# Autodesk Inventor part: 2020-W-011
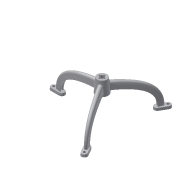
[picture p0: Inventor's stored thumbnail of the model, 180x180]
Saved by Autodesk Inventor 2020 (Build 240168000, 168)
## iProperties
Created: 2013-12
Part Number: 2020-W-011
Material: Tworzywo o ultrawysokiej masie cząsteczkowej, białe
Document SubType Name: Modeling
Designer: F.Stasiak
Density: 0.94 g/cm^3
Appearance: Gładki - biały
Manager: www.cadconsulting.pl
Company: Fabian Stasiak CAD Consulting
Author: F.Stasiak
Subject: Zbiór ćwiczeń. Autodesk Inventor 2020. Kurs podstawowy
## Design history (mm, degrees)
sketch "Szkic1"
  geometry: L1 (20.99, 0)-(-20.99, 0); L2 (-150, -53.809)-(-150, -106.191); A1 r 277.438 centre (0, -277.438) between (16.762, -0.507) and (-16.762, -0.507); A2 r 89.469 centre (-60.531, -80) between (-147.643, -59.599) and (-147.643, -100.401); 3 further points
  constraints: 4 end point, 4 midpoint, 2 centre point, 2 horizontal, 2 point on circle, 2 vertical, 5 other
  dimensions: "d1" = 80 vertical distance of point (-150, -80) point (0, 0); "d2" = 150 horizontal distance of point (-150, -80) point (0, 0)
node "Płaszczyzna konstrukcyjna1"
sketch "Szkic2"
  geometry: L1 (0, -10)-(0, -4); L2 (0, 10)-(-20.781, 7.962); L3 (-20.781, -7.962)-(0, -10); L4 (0, -4)-(-10.293, -2.99); L5 (-10.293, 2.99)-(0, 4); L6 (0, -4)-(0, 4); L7 (0, 4)-(0, 10); A1 r 8 centre (-20, 0) between (-20.781, 7.962) and (-20.781, -7.962); A2 r 3.005 centre (-10, 0) between (-10.293, 2.99) and (-10.293, -2.99); 3 further points
  constraints: 14 end point, 4 point on circle, 4 tangent, 3 vertical, 2 centre point, 2 coincident, 2 horizontal alignment, 2 parallel, 1 collinear, 1 midpoint, 1 point on line
  dimensions: "d3" = 8 radius of A1; "d4" = 20 distance from line of A1.centre L1; "d5" = 20 distance of L1.start L2.start; "d62" = 10 distance of A2.centre point (0, 0); "d63" = 8 distance of L5.end L1.end
node "Płaszczyzna konstrukcyjna2"
sketch "Szkic3"
  geometry: L1 (0, -7.5)-(0, -3); L2 (0, 7.5)-(-15.801, 4.935); L3 (-15.801, -4.935)-(0, -7.5); L4 (0, -3)-(-8.269, -1.658); L5 (-8.269, 1.658)-(0, 3); L6 (0, -3)-(0, 3); L7 (0, 3)-(0, 7.5); A1 r 5 centre (-15, 0) between (-15.801, 4.935) and (-15.801, -4.935); A2 r 1.68 centre (-8, 0) between (-8.269, 1.658) and (-8.269, -1.658); 4 further points
  constraints: 14 end point, 4 point on circle, 4 tangent, 3 vertical, 2 centre point, 2 coincident, 2 horizontal alignment, 2 parallel, 1 collinear, 1 midpoint, 1 point on line
  dimensions: "d6" = 5 radius of A1; "d7" = 15 distance from line of A1.centre L1; "d9" = 15 distance of L1.start L2.start; "d64" = 6 distance of L5.end L1.end; "d65" = 8 distance from line of L1 A2.centre
feature "Wyciągnięcie złożone1" sketch "Szkic3" dims "d10" = 0, "d11" = 90 deg, "d12" = 0, "d13" = 90 deg, "d14" = 0, "d15" = 90 deg
sketch "Szkic8"
  geometry: L1 (0, 10.5)-(0, 15) reference; L2 (0, 10.5)-(0, 4.5); L3 (0, 7.5)-(-30, 7.5); L4 (0, 17.5)-(-30, 17.5); L5 (-30, -2.5)-(0, -2.5); A1 r 10 centre (0, 7.5) between (0, -2.5) and (0, 17.5); A2 r 10 centre (-30, 7.5) between (-30, 17.5) and (-30, -2.5); 2 further points
  constraints: 10 end point, 4 point on circle, 4 tangent, 2 centre point, 2 midpoint, 1 collinear, 1 parallel, 1 perpendicular
  dimensions: "d71" = 30 distance of L3.start L3.end; "d72" = 20 diameter of A2
extrude "Wyciągnięcie proste3" join sketch "Szkic8" distance "d68" = 10; taper "d69" = 5 deg
hole "Otwór2" diameter "d75" = 9; stored, may be unused: countersink angle "d79" = 90 deg, drill point angle "d81" = 118 deg; dims "d73" = 10, "d74" = 10, "d76" = 6, "d77" = 4, "d78" = 2, "d80" = 8
fillet "Zaokrąglenie7" dims "d82" = 1
fillet "Zaokrąglenie8" dims "d83" = 1
chamfer "Faza1" distance "d84" = 1; stored, may be unused: second distance "d85" = 2, angle "d86" = 45 deg
pattern_circular "Szyk kołowy2" dims "d39" = 360 deg
node "Płaszczyzna konstrukcyjna3"
sketch "Szkic10"
  geometry: C1 r 22.5 at (0, 0); 1 further point
  constraints: 1 centre point, 1 coincident
  dimensions: "d102" = 45 diameter of C1
extrude "Wyciągnięcie proste5" join sketch "Szkic10" distance "d103" = 50; taper "d104" = -5 deg
sketch "Szkic11"
  geometry: L1 (-11.5, 2.5)-(11.5, 2.5); L2 (11.5, 2.5)-(11.5, -2.5); L3 (11.5, -2.5)-(-11.5, -2.5); L4 (-11.5, -2.5)-(-11.5, 2.5); L5 (-11.5, 2.5)-(11.5, -2.5); L6 (11.5, 2.5)-(-11.5, -2.5); L7 (-2.5, -11.5)-(2.5, -11.5); L8 (2.5, -11.5)-(2.5, 11.5); L9 (2.5, 11.5)-(-2.5, 11.5); L10 (-2.5, 11.5)-(-2.5, -11.5); L11 (-2.5, -11.5)-(2.5, 11.5); L12 (2.5, -11.5)-(-2.5, 11.5); C1 r 18.126 at (0, 0) reference; C2 r 8 at (0, 0)
  constraints: 24 end point, 4 midpoint, 4 parallel, 2 horizontal, 2 perpendicular, 1 centre point, 1 coincident
  dimensions: "d105" = 16 diameter of C2; "d106" = 23 distance of L2.end L3.end; "d107" = 5 distance of L1.end L2.end; "d108" = 5 distance of L9.end L8.end; "d109" = 23 distance of L8.end L7.end
extrude "Wyciągnięcie proste6" cut sketch "Szkic11" extent not by distance; stored distance "d110" = 50; taper "d111" = 0 deg
fillet "Zaokrąglenie10" dims "d112" = 4
node "Bryła1"
